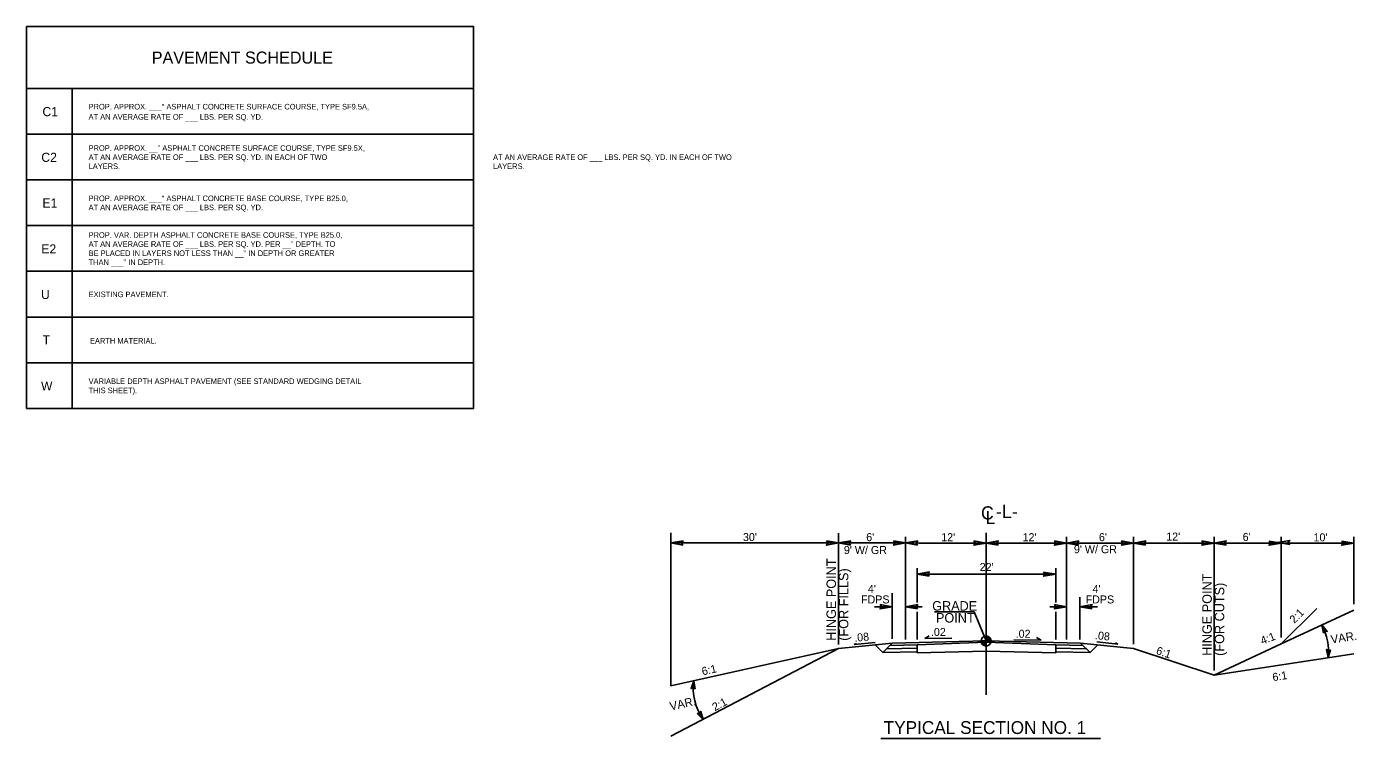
# Model space of a CAD drawing. Extents: x 1718167 to 1721223, y 797898 to 799800.
# Drawn here: x 1718976 to 1720166, y 799163 to 799800 of the extents above; entities that cross this region are included whole.
import ezdxf

# ---------------------------------------------------------------- set-up
doc = ezdxf.new("R2010")
doc.units = 0
for name, color, linetype in [('Old_Level_1', 7, 'Continuous'), ('Old_Level_2', 7, 'Continuous'), ('Prop Dimension Text', 7, 'Continuous'), ('Prop Pavement Schedule Description CELL', 7, 'Continuous'), ('Prop Terminator CELL', 7, 'Continuous'), ('Typical Slope Point Local CELL', 7, 'Continuous'), ('Typical Terminator CELL', 7, 'Continuous'), ('Typical Text Centerline CELL', 7, 'Continuous'), ('Typical Text Grade Point CELL', 7, 'Continuous'), ('Typical Text Label CELL', 7, 'Continuous')]:
    doc.layers.add(name, color=color, linetype=linetype)

# ---------------------------------------------------------------- blocks, each defined once
blk = doc.blocks.new('TERMINATOR')
at = {"layer": 'Typical Terminator CELL'}
blk.add_lwpolyline([(-0.469, 0.081), (0, 0), (-0.471, -0.083), (-0.411, 0)], close=True, dxfattribs=at)

msp = doc.modelspace()

# ---------------------------------------------------------------- linework, layer by layer
at = {"layer": 'Old_Level_1'}
for p, q in [((1719552.3, 799210.3), (1719552.3, 799347)), ((1719702.3, 799247.1), (1719702.3, 799346.9)), ((1719762.3, 799251.7), (1719762.3, 799343.5)), ((1719906.3, 799251.7), (1719906.3, 799343.4)), ((1719966.3, 799247.4), (1719966.3, 799343.4)), ((1720038.3, 799224), (1720038.3, 799343.4)), ((1720098.3, 799253.5), (1720098.3, 799343.4)), ((1720163.3, 799283.3), (1720163.3, 799343.4)), ((1719702.3, 799338), (1719552.3, 799338)), ((1719762.3, 799338), (1719702.3, 799338)), ((1719834.3, 799337.9), (1719762.3, 799338)), ((1719774.3, 799337.9), (1719834.3, 799337.9)), ((1719906.3, 799337.9), (1719834.3, 799337.9)), ((1719906.3, 799337.9), (1719966.3, 799337.9)), ((1719966.3, 799337.9), (1720038.3, 799337.9)), ((1720038.3, 799337.9), (1720098.3, 799337.9)), ((1720098.3, 799337.9), (1720163.3, 799337.9)), ((1719772.6, 799284.8), (1719772.6, 799315.4)), ((1719896.6, 799310.1), (1719772.6, 799310.2)), ((1719896.6, 799284.8), (1719896.6, 799315.4)), ((1719750.3, 799252.2), (1719750.3, 799293)), ((1719918.3, 799251.7), (1719918.3, 799289.6)), ((1719734.6, 799280.9), (1719750.3, 799280.9)), ((1719762.3, 799280.9), (1719777.1, 799280.9)), ((1719772.6, 799251.7), (1719772.6, 799276.5)), ((1719788.1, 799276.4), (1719823.8, 799276.4)), ((1719823.8, 799276.4), (1719834.3, 799250.3)), ((1719906.3, 799280.9), (1719891.5, 799280.9)), ((1719896.6, 799251.7), (1719896.6, 799276.5)), ((1719934.1, 799280.9), (1719918.3, 799280.9)), ((1719750.3, 799248.5), (1719720.5, 799245.5)), ((1719829.8, 799250.3), (1719834.3, 799250.3)), ((1719834.3, 799250.3), (1719834.3, 799254.8)), ((1719838.8, 799250.3), (1719834.3, 799250.3)), ((1719834.3, 799245.8), (1719834.3, 799250.3)), ((1719834.3, 799250.3), (1719834.3, 799245.8)), ((1719966.3, 799243.7), (1719918.9, 799248.5)), ((1719933.4, 799249.5), (1719952.1, 799247.6)), ((1719952.1, 799247.6), (1719950.1, 799248.6)), ((1719720.5, 799245.5), (1719702.3, 799243.7)), ((1719966.3, 799243.7), (1720038.3, 799219.7))]:
    msp.add_line(p, q, dxfattribs=at)
for points in [[(1719829.8, 799250.3), (1719829.8, 799249.8)], [(1719829.9, 799250.3), (1719829.9, 799249.3)], [(1719830, 799250.3), (1719830, 799249)], [(1719830.1, 799250.3), (1719830.1, 799248.7)], [(1719830.2, 799250.3), (1719830.2, 799248.5)], [(1719830.3, 799250.3), (1719830.3, 799248.3)], [(1719830.4, 799250.3), (1719830.4, 799248.1)], [(1719830.5, 799250.3), (1719830.5, 799248)], [(1719830.6, 799250.3), (1719830.6, 799247.8)], [(1719830.7, 799250.3), (1719830.7, 799247.7)], [(1719830.7, 799250.3), (1719830.7, 799247.6)], [(1719830.8, 799250.3), (1719830.8, 799247.5)], [(1719830.9, 799250.3), (1719830.9, 799247.3)], [(1719831, 799250.3), (1719831, 799247.2)], [(1719831.1, 799250.3), (1719831.1, 799247.1)], [(1719831.2, 799250.3), (1719831.2, 799247.1)], [(1719831.3, 799250.3), (1719831.3, 799247)], [(1719831.4, 799250.3), (1719831.4, 799246.9)], [(1719831.5, 799250.3), (1719831.5, 799246.8)], [(1719831.6, 799250.3), (1719831.6, 799246.7)], [(1719831.6, 799250.3), (1719831.6, 799246.7)], [(1719831.7, 799250.3), (1719831.7, 799246.6)], [(1719831.8, 799250.3), (1719831.8, 799246.6)], [(1719831.9, 799250.3), (1719831.9, 799246.5)], [(1719832, 799250.3), (1719832, 799246.4)], [(1719832.1, 799250.3), (1719832.1, 799246.4)], [(1719832.2, 799250.3), (1719832.2, 799246.3)], [(1719832.3, 799250.3), (1719832.3, 799246.3)], [(1719832.4, 799250.3), (1719832.4, 799246.2)], [(1719832.5, 799250.3), (1719832.5, 799246.2)], [(1719832.5, 799250.3), (1719832.5, 799246.2)], [(1719832.6, 799250.3), (1719832.6, 799246.1)], [(1719832.7, 799250.3), (1719832.7, 799246.1)], [(1719832.8, 799250.3), (1719832.8, 799246.1)], [(1719832.9, 799250.3), (1719832.9, 799246)], [(1719833, 799250.3), (1719833, 799246)], [(1719833.1, 799250.3), (1719833.1, 799246)], [(1719833.2, 799250.3), (1719833.2, 799245.9)], [(1719833.3, 799250.3), (1719833.3, 799245.9)], [(1719833.4, 799250.3), (1719833.4, 799245.9)], [(1719833.4, 799250.3), (1719833.4, 799245.9)], [(1719833.5, 799250.3), (1719833.5, 799245.9)], [(1719833.6, 799250.3), (1719833.6, 799245.9)], [(1719833.7, 799250.3), (1719833.7, 799245.8)], [(1719833.8, 799250.3), (1719833.8, 799245.8)], [(1719833.9, 799250.3), (1719833.9, 799245.8)], [(1719834, 799250.3), (1719834, 799245.8)], [(1719834.1, 799250.3), (1719834.1, 799245.8)], [(1719834.2, 799250.3), (1719834.2, 799245.8)], [(1719834.3, 799250.3), (1719834.3, 799245.8), (1719834.3, 799245.8)], [(1719834.4, 799254.8), (1719834.4, 799254.8), (1719834.4, 799250.3)], [(1719834.5, 799254.8), (1719834.5, 799250.3)], [(1719834.5, 799254.8), (1719834.5, 799250.3)], [(1719834.6, 799254.8), (1719834.6, 799250.3)], [(1719834.7, 799254.8), (1719834.7, 799250.3)], [(1719834.8, 799254.8), (1719834.8, 799250.3)], [(1719834.9, 799254.8), (1719834.9, 799250.3)], [(1719835, 799254.7), (1719835, 799250.3)], [(1719835.1, 799254.7), (1719835.1, 799250.3)], [(1719835.2, 799254.7), (1719835.2, 799250.3)], [(1719835.3, 799254.7), (1719835.3, 799250.3)], [(1719835.4, 799254.7), (1719835.4, 799250.3)], [(1719835.4, 799254.7), (1719835.4, 799250.3)], [(1719835.5, 799254.6), (1719835.5, 799250.3)], [(1719835.6, 799254.6), (1719835.6, 799250.3)], [(1719835.7, 799254.6), (1719835.7, 799250.3)], [(1719835.8, 799254.5), (1719835.8, 799250.3)], [(1719835.9, 799254.5), (1719835.9, 799250.3)], [(1719836, 799254.5), (1719836, 799250.3)], [(1719836.1, 799254.4), (1719836.1, 799250.3)], [(1719836.2, 799254.4), (1719836.2, 799250.3)], [(1719836.3, 799254.4), (1719836.3, 799250.3)], [(1719836.3, 799254.3), (1719836.3, 799250.3)], [(1719836.4, 799254.3), (1719836.4, 799250.3)], [(1719836.5, 799254.2), (1719836.5, 799250.3)], [(1719836.6, 799254.2), (1719836.6, 799250.3)], [(1719836.7, 799254.1), (1719836.7, 799250.3)], [(1719836.8, 799254.1), (1719836.8, 799250.3)], [(1719836.9, 799254), (1719836.9, 799250.3)], [(1719837, 799253.9), (1719837, 799250.3)], [(1719837.1, 799253.9), (1719837.1, 799250.3)], [(1719837.2, 799253.8), (1719837.2, 799250.3)], [(1719837.2, 799253.7), (1719837.2, 799250.3)], [(1719837.3, 799253.6), (1719837.3, 799250.3)], [(1719837.4, 799253.6), (1719837.4, 799250.3)], [(1719837.5, 799253.5), (1719837.5, 799250.3)], [(1719837.6, 799253.4), (1719837.6, 799250.3)], [(1719837.7, 799253.3), (1719837.7, 799250.3)], [(1719837.8, 799253.2), (1719837.8, 799250.3)], [(1719837.9, 799253.1), (1719837.9, 799250.3)], [(1719838, 799252.9), (1719838, 799250.3)], [(1719838.1, 799252.8), (1719838.1, 799250.3)], [(1719838.1, 799252.7), (1719838.1, 799250.3)], [(1719838.2, 799252.5), (1719838.2, 799250.3)], [(1719838.3, 799252.4), (1719838.3, 799250.3)], [(1719838.4, 799252.2), (1719838.4, 799250.3)], [(1719838.5, 799252), (1719838.5, 799250.3)], [(1719838.6, 799251.7), (1719838.6, 799250.3)], [(1719838.7, 799251.4), (1719838.7, 799250.3)], [(1719838.8, 799250.9), (1719838.8, 799250.3)]]:
    msp.add_lwpolyline(points, dxfattribs=at)
msp.add_circle((1719834.3, 799250.3), 4.5, dxfattribs=at)
for start, end in [(179.9785, 269.9785), (359.9785, 89.9785)]:
    msp.add_arc((1719834.3, 799250.3), 4.5, start, end, dxfattribs=at)
at = {"layer": 'Old_Level_2'}
for p, q in [((1719716.4, 799247.2), (1719735.2, 799249)), ((1719716.4, 799247.2), (1719718.5, 799248.2)), ((1719779.4, 799252.4), (1719783.5, 799254.9)), ((1719779.4, 799252.4), (1719803.7, 799252.9)), ((1719883.6, 799250.9), (1719859.3, 799251.3)), ((1719883.6, 799250.9), (1719879.5, 799253.3))]:
    msp.add_line(p, q, dxfattribs=at)
at = {"layer": 'Prop Dimension Text'}
for centre, start, end in [((1720091.2, 799240.9), 353.644, 28.6699), ((1719621.9, 799208.4), 172.5997, 214.6638)]:
    msp.add_arc(centre, 49.6, start, end, dxfattribs=at)
at = {"layer": 'Prop Pavement Schedule Description CELL'}
msp.add_lwpolyline([(1718975.8, 799799.9), (1719375.8, 799799.9), (1719375.8, 799744.7), (1718975.8, 799744.7)], close=True, dxfattribs=at)
for points in [[(1719016.7, 799703.8), (1718975.8, 799703.8), (1718975.8, 799744.7), (1719375.8, 799744.7), (1719375.8, 799703.8), (1719016.7, 799703.8), (1719016.7, 799744.7)], [(1719016.7, 799662.9), (1718975.8, 799662.9), (1718975.8, 799703.8), (1719375.8, 799703.8), (1719375.8, 799662.9), (1719016.7, 799662.9), (1719016.7, 799703.8)], [(1719016.7, 799622), (1718975.8, 799622), (1718975.8, 799662.9), (1719375.8, 799662.9), (1719375.8, 799622), (1719016.7, 799622), (1719016.7, 799662.9)], [(1719016.7, 799581.1), (1718975.8, 799581.1), (1718975.8, 799622), (1719375.8, 799622), (1719375.8, 799581.1), (1719016.7, 799581.1), (1719016.7, 799622)], [(1719016.7, 799540.1), (1718975.8, 799540.1), (1718975.8, 799581.1), (1719375.8, 799581.1), (1719375.8, 799540.1), (1719016.7, 799540.1), (1719016.7, 799581.1)], [(1719016.7, 799499.2), (1718975.8, 799499.2), (1718975.8, 799540.1), (1719375.8, 799540.1), (1719375.8, 799499.2), (1719016.7, 799499.2), (1719016.7, 799540.1)], [(1719016.7, 799458.3), (1718975.8, 799458.3), (1718975.8, 799499.2), (1719375.8, 799499.2), (1719375.8, 799458.3), (1719016.7, 799458.3), (1719016.7, 799499.2)]]:
    msp.add_lwpolyline(points, dxfattribs=at)
at = {"layer": 'Prop Terminator CELL'}
for points in [[(1719563.1, 799336.1), (1719552.3, 799338), (1719563.2, 799339.9), (1719561.8, 799338)], [(1719691.5, 799339.8), (1719702.3, 799338), (1719691.5, 799336), (1719692.9, 799338)], [(1719713.1, 799336.1), (1719702.3, 799338), (1719713.2, 799339.9), (1719711.8, 799338)], [(1719751.5, 799339.8), (1719762.3, 799338), (1719751.5, 799336), (1719752.9, 799338)], [(1719773.1, 799336.1), (1719762.3, 799338), (1719773.2, 799339.9), (1719771.8, 799337.9)], [(1719823.5, 799339.8), (1719834.3, 799337.9), (1719823.5, 799336), (1719824.9, 799337.9)], [(1719845.1, 799336.1), (1719834.3, 799337.9), (1719845.2, 799339.9), (1719843.8, 799337.9)], [(1719895.5, 799339.8), (1719906.3, 799337.9), (1719895.5, 799336), (1719896.9, 799337.9)], [(1719917.1, 799336.1), (1719906.3, 799337.9), (1719917.2, 799339.8), (1719915.8, 799337.9)], [(1719955.5, 799339.8), (1719966.3, 799337.9), (1719955.5, 799336), (1719956.9, 799337.9)], [(1719977.1, 799336), (1719966.3, 799337.9), (1719977.2, 799339.8), (1719975.8, 799337.9)], [(1720027.5, 799339.8), (1720038.3, 799337.9), (1720027.5, 799336), (1720028.9, 799337.9)], [(1720049.1, 799336), (1720038.3, 799337.9), (1720049.2, 799339.8), (1720047.8, 799337.9)], [(1720087.5, 799339.7), (1720098.3, 799337.9), (1720087.5, 799336), (1720088.9, 799337.9)], [(1720106, 799336.6), (1720095.2, 799338.4), (1720106.1, 799340.3), (1720104.7, 799338.4)], [(1720152.5, 799339.7), (1720163.3, 799337.9), (1720152.5, 799335.9), (1720153.9, 799337.9)], [(1719783.4, 799308.3), (1719772.6, 799310.2), (1719783.5, 799312.1), (1719782.1, 799310.2)], [(1719885.8, 799312), (1719896.6, 799310.1), (1719885.8, 799308.2), (1719887.2, 799310.1)], [(1719739.5, 799282.8), (1719750.3, 799280.9), (1719739.5, 799279), (1719740.8, 799280.9)], [(1719773.1, 799279.1), (1719762.3, 799280.9), (1719773.2, 799282.9), (1719771.8, 799280.9)], [(1719895.5, 799282.8), (1719906.3, 799280.9), (1719895.5, 799279), (1719896.8, 799280.9)], [(1719929.1, 799279), (1719918.3, 799280.9), (1719929.2, 799282.8), (1719927.8, 799280.9)]]:
    msp.add_lwpolyline(points, close=True, dxfattribs=at)
at = {"layer": 'Typical Slope Point Local CELL'}
for p, q in [((1720130.2, 799279.5), (1720098.3, 799247.7)), ((1720163.3, 799278), (1720098.3, 799247.7)), ((1719750.3, 799248.5), (1719741.8, 799240.1)), ((1719750.3, 799248.5), (1719834.3, 799250.3)), ((1719772.6, 799246.8), (1719834.3, 799249.2)), ((1719834.3, 799250.3), (1719918.9, 799248.5)), ((1719834.3, 799249.2), (1719896.6, 799246.8)), ((1719918.9, 799248.5), (1719927.4, 799240)), ((1719552.3, 799210.3), (1719702.3, 799243.7)), ((1719552.3, 799165.1), (1719702.3, 799243.7)), ((1719741.8, 799240.1), (1719735.2, 799247)), ((1719741.8, 799240.1), (1719772.6, 799240.7)), ((1719745.2, 799243.4), (1719772.6, 799244)), ((1719748.1, 799246.3), (1719772.6, 799246.8)), ((1719772.6, 799246.8), (1719772.6, 799239.8)), ((1719772.6, 799239.8), (1719834.3, 799241.1)), ((1719834.3, 799241.1), (1719896.6, 799239.8)), ((1719896.6, 799246.8), (1719896.6, 799239.8)), ((1719896.6, 799246.8), (1719921.1, 799246.3)), ((1719896.6, 799244), (1719924, 799243.4)), ((1719896.6, 799240.7), (1719927.4, 799240)), ((1719927.4, 799240), (1719934.3, 799247)), ((1720098.3, 799247.7), (1720038.3, 799219.7)), ((1720163.3, 799238.9), (1720038.3, 799219.7)), ((1719740.3, 799163.2), (1719740.3, 799163.2)), ((1719740.3, 799163.2), (1719740.3, 799163.2)), ((1719740.3, 799163.2), (1719740.3, 799163.2)), ((1719740.3, 799163.2), (1719740.3, 799163.2)), ((1719740.3, 799163.2), (1719740.3, 799163.2)), ((1719740.3, 799163.2), (1719740.3, 799163.2)), ((1719740.3, 799163.2), (1719740.3, 799163.2))]:
    msp.add_line(p, q, dxfattribs=at)
at = {"layer": 'Typical Text Centerline CELL'}
msp.add_line((1719834.3, 799202), (1719834.3, 799347), dxfattribs=at)
at = {"layer": 'Typical Text Label CELL'}
msp.add_line((1719740.3, 799163.2), (1719936.6, 799163.2), dxfattribs=at)

# ---------------------------------------------------------------- block references
at = {"layer": 'Prop Dimension Text'}
for p, xscale, yscale, rotation in [((1720134.8, 799264.7), 15.392576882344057, 22.093150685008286, 114.95593900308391), ((1720140.5, 799235.4), 15.392576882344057, 22.09315068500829, -92.46700988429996), ((1719572.7, 799214.8), 15.392576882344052, -22.093150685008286, 86.31361772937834), ((1719581.1, 799180.2), 15.392576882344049, -22.093150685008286, -59.199412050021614)]:
    msp.add_blockref('TERMINATOR', p, dxfattribs=dict(at, xscale=xscale, yscale=yscale, rotation=rotation))

# ---------------------------------------------------------------- texts
at = {"layer": 'Old_Level_1'}
for s, rotation, p in [("30'", 359.988, (1719616.8, 799339.7)), ("6'", 359.988, (1719727.1, 799339.6)), ("12'", 359.988, (1719794.2, 799339.6)), ("12'", 359.988, (1719867, 799339.6)), ("6'", 359.988, (1719935.3, 799339.6)), ("12'", 359.988, (1719995.5, 799340.1)), ("6'", 359.988, (1720063.9, 799339.8)), ("10'", 359.988, (1720127.3, 799339.4)), ("9' W/ GR", 359.988, (1719707.1, 799328.1)), ("9' W/ GR", 359.988, (1719912.9, 799328.8)), ("22'", 359.988, (1719828.6, 799312.9)), (" 4' ", 359.988, (1719725.9, 799293.3)), (" 4' ", 359.9878, (1719926.9, 799293.3)), ('FDPS', 359.988, (1719722.4, 799283.9)), ('FDPS', 359.9878, (1719923.4, 799283.9))]:
    msp.add_text(s, height=7.16, rotation=rotation, dxfattribs=at).set_placement(p)
at = {"layer": 'Old_Level_2'}
for rotation, p in [(5.7484, (1719716.7, 799249.5)), (354.2008, (1719931.5, 799252))]:
    msp.add_text('.08 ', height=7.16, rotation=rotation, dxfattribs=at).set_placement(p)
at = {"layer": 'Prop Dimension Text'}
for s, height, rotation, p in [('GRADE', 8.47, 359.988, (1719786.1, 799277.5)), ('POINT', 8.47, 359.988, (1719789.5, 799266.8)), ('.02', 7.16, 359.988, (1719785, 799254.8)), ('.02', 7.16, 359.988, (1719860.8, 799253.2)), ('6:1', 7.16, 341.5531, (1719985.9, 799238.8))]:
    msp.add_text(s, height=height, rotation=rotation, dxfattribs=at).set_placement(p)
at = {"layer": 'Prop Pavement Schedule Description CELL'}
for s, height, p in [('PAVEMENT SCHEDULE', 10.8, (1719087.8, 799766.8)), ('C1', 8.17, (1718990, 799719.8)), ('PROP. APPROX. ___" ASPHALT CONCRETE SURFACE COURSE, TYPE SF9.5A,', 5, (1719031.3, 799725.8)), ('AT AN AVERAGE RATE OF ___ LBS. PER SQ. YD.', 5, (1719031.3, 799716.6)), ('PROP. APPROX. __" ASPHALT CONCRETE SURFACE COURSE, TYPE SF9.5X, ', 5, (1719031.3, 799688.8)), ('C2', 8.17, (1718989, 799678.9)), ('AT AN AVERAGE RATE OF ___ LBS. PER SQ. YD. IN EACH OF TWO ', 5, (1719031.3, 799680.6)), ('LAYERS.', 5, (1719031.3, 799672.5)), ('AT AN AVERAGE RATE OF ___ LBS. PER SQ. YD. IN EACH OF TWO ', 5, (1719393.2, 799680.6)), ('LAYERS.', 5, (1719393.2, 799672.5)), ('E1', 8.17, (1718990, 799638)), ('AT AN AVERAGE RATE OF ___ LBS. PER SQ. YD.', 5, (1719031.3, 799635.7)), ('PROP. APPROX. ___" ASPHALT CONCRETE BASE COURSE, TYPE B25.0,', 5, (1719031.3, 799643.8)), ('E2', 8.17, (1718989, 799597)), ('AT AN AVERAGE RATE OF ___ LBS. PER SQ. YD. PER __" DEPTH. TO', 5, (1719031.3, 799602.9)), ('PROP. VAR. DEPTH ASPHALT CONCRETE BASE COURSE, TYPE B25.0,', 5, (1719031.3, 799611)), ('BE PLACED IN LAYERS NOT LESS THAN __" IN DEPTH OR GREATER', 5, (1719031.3, 799594.7)), ('THAN ___" IN DEPTH.', 5, (1719031.3, 799586.6)), ('U ', 8, (1718988.8, 799556.2)), ('EXISTING PAVEMENT.', 5, (1719031.3, 799557.9)), ('T ', 8, (1718990.2, 799515.6)), ('EARTH MATERIAL.', 5, (1719032.5, 799516.3)), ('W ', 8, (1718988.8, 799474.4)), ('VARIABLE DEPTH ASPHALT PAVEMENT (SEE STANDARD WEDGING DETAIL', 5, (1719031.3, 799480.2)), ('THIS SHEET).', 5, (1719031.3, 799472))]:
    msp.add_text(s, height=height, dxfattribs=at).set_placement(p)
at = {"layer": 'Typical Slope Point Local CELL'}
for s, height, rotation, p in [('HINGE POINT', 8.467, 90, (1719700, 799250.5)), ('(FOR FILLS)', 8.467, 90, (1719711.1, 799250.5)), ('HINGE POINT', 8.467, 90, (1720036.3, 799237)), ('(FOR CUTS)', 8.47, 90, (1720047.4, 799237)), ('2:1', 7.16, 44.9549, (1720110.1, 799265.5)), ('4:1', 7.16, 21.2393, (1720081.5, 799246.9)), ('VAR. ', 7.56, 8.7105, (1720143.3, 799247.9)), ('6:1', 7.16, 12.559, (1719580.8, 799219.5)), ('6:1', 7.16, 8.7105, (1720091.1, 799214.3)), ('VAR. ', 7.56, 12.559, (1719552.2, 799188)), ('2:1', 7.16, 27.6461, (1719591.6, 799187.4))]:
    msp.add_text(s, height=height, rotation=rotation, dxfattribs=at).set_placement(p)
at = {"layer": 'Typical Text Centerline CELL'}
msp.add_text('C', height=11.8, dxfattribs=at).set_placement((1719829.8, 799359))
msp.add_text('L', height=11.8, rotation=359.9469, dxfattribs=at).set_placement((1719833.8, 799354.9))
at = {"layer": 'Typical Text Grade Point CELL'}
msp.add_text('-L-', height=12, dxfattribs=at).set_placement((1719843.1, 799360.2))
at = {"layer": 'Typical Text Label CELL'}
msp.add_text('TYPICAL SECTION NO. 1', height=11.5, dxfattribs=at).set_placement((1719742.7, 799167.1))

doc.saveas('drawing.dxf')
